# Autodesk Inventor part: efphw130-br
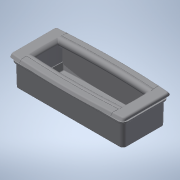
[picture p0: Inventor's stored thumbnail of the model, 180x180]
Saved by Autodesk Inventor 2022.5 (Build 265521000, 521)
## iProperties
Created: 2016-12
Part Number: efphw130-br
Material: 一般
Document SubType Name: Modeling
Designer: imaocorp
Density: 1 g/cm^3
Appearance: 既定
Author: imaocorp
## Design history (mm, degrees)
node "efphw130-br.x_t1"
node "Part26"
node "Base1"
